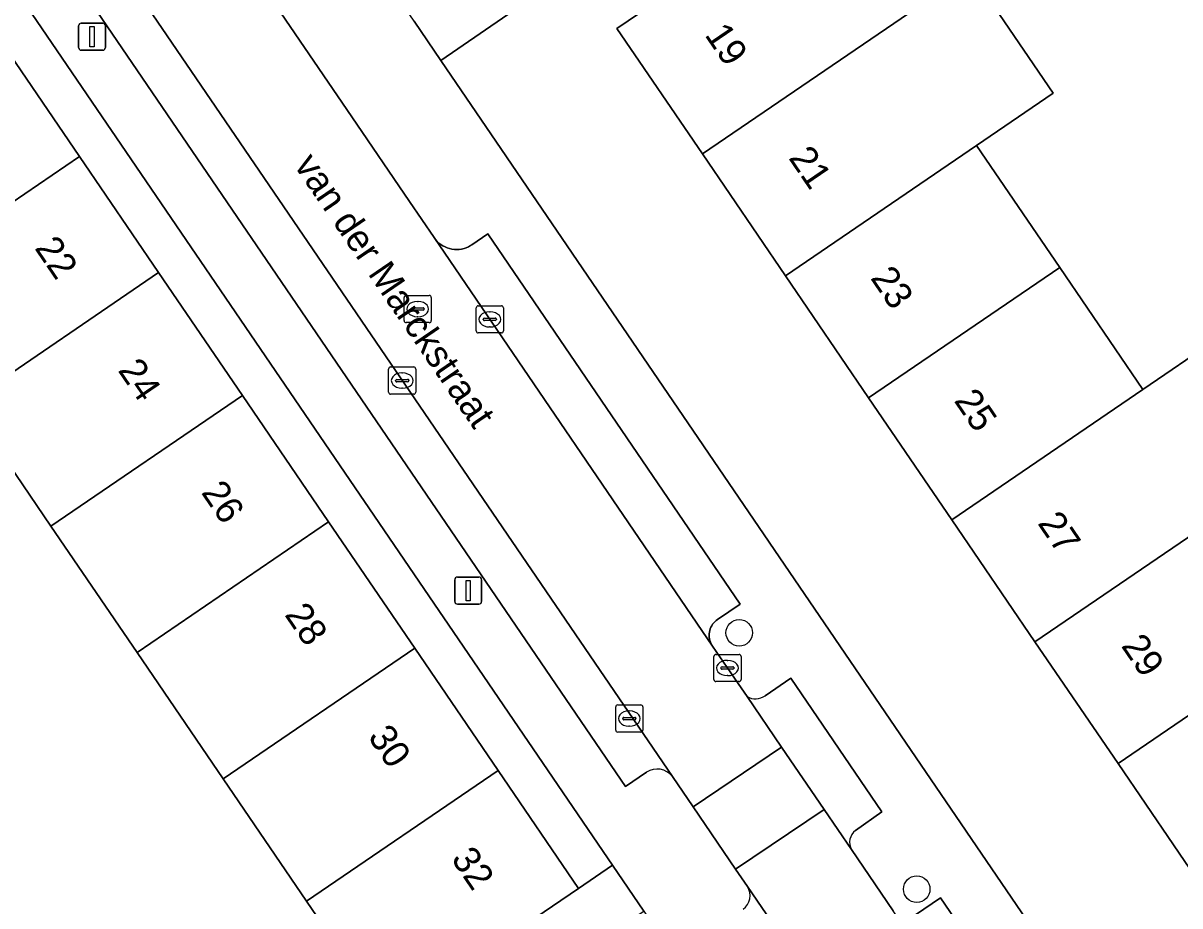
# Model space of a CAD drawing. Extents: x 157445 to 158888, y 383061 to 384688.
# Drawn here: x 158205.18 to 158247.77, y 383821.51 to 383854 of the extents above; entities that cross this region are included whole.
import ezdxf

# ---------------------------------------------------------------- set-up
doc = ezdxf.new("R2010")
doc.units = 0
for name, color, linetype in [('IMGEO_Boom', 7, 'Continuous'), ('IMGEO_Erf', 7, 'Continuous'), ('IMGEO_Kolk', 7, 'Continuous'), ('IMGEO_Lichtmast', 7, 'Continuous'), ('IMGEO_Openbare_ruimte_label', 7, 'Continuous'), ('IMGEO_Pand', 7, 'Continuous'), ('IMGEO_Pand_nummerreeks', 7, 'Continuous'), ('IMGEO_Parkeervlak_open', 7, 'Continuous'), ('IMGEO_Rijbaan_lokaal_open', 7, 'Continuous'), ('IMGEO_Rioolput', 7, 'Continuous'), ('IMGEO_Voetpad_open', 7, 'Continuous')]:
    doc.layers.add(name, color=color, linetype=linetype)

msp = doc.modelspace()

# ---------------------------------------------------------------- linework, layer by layer
at = {"layer": 'IMGEO_Boom'}
for centre in [(158231.547, 383831.557), (158238.081, 383822.12)]:
    msp.add_circle(centre, 0.489, dxfattribs=at)
at = {"layer": 'IMGEO_Erf'}
msp.add_lwpolyline([(158196.185, 383867.993), (158194.952, 383867.112), (158198.052, 383862.567), (158201.186, 383857.973), (158204.125, 383853.665), (158207.248, 383849.087), (158210.162, 383844.815), (158213.249, 383840.289), (158216.423, 383835.636), (158219.595, 383830.987), (158222.667, 383826.484), (158225.623, 383822.15), (158226.875, 383823.004)], close=True, dxfattribs=at)
for points in [[(158238.26, 383864.78), (158220.561, 383852.622), (158254.415, 383802.985), (158261.257, 383807.652), (158259.697, 383809.94), (158257.824, 383808.662), (158254.679, 383813.274), (158251.618, 383817.762), (158248.556, 383822.251), (158245.495, 383826.74), (158242.434, 383831.228), (158239.373, 383835.717), (158236.312, 383840.206), (158233.251, 383844.694), (158230.19, 383849.182), (158227.044, 383853.795), (158231.175, 383856.612)], [(158240.051, 383855.907), (158243.112, 383851.419), (158240.288, 383849.493), (158243.349, 383845.004), (158246.411, 383840.515), (158249.066, 383842.326)], [(158201.602, 383814.959), (158205.919, 383808.565), (158206.186, 383808.753), (158203.229, 383812.949), (158205.689, 383814.682), (158208.646, 383810.486), (158218.573, 383817.34), (158215.617, 383821.674), (158212.545, 383826.177), (158209.373, 383830.826), (158206.199, 383835.479), (158203.111, 383840.006)]]:
    msp.add_lwpolyline(points, dxfattribs=at)
at = {"layer": 'IMGEO_Kolk'}
for p, q in [((158221.862, 383842.667), (158221.862, 383843.519)), ((158221.937, 383843.593), (158222.789, 383843.593)), ((158222.863, 383843.519), (158222.863, 383842.667)), ((158222.121, 383843.087), (158222.121, 383843.099)), ((158222.559, 383843.05), (158222.161, 383843.05)), ((158222.164, 383843.136), (158222.562, 383843.136)), ((158222.35, 383843.373), (158222.375, 383843.373)), ((158222.605, 383843.099), (158222.605, 383843.087)), ((158222.373, 383842.813), (158222.348, 383842.813)), ((158222.789, 383842.593), (158221.937, 383842.593)), ((158218.71, 383841.34), (158219.562, 383841.34)), ((158218.635, 383840.414), (158218.635, 383841.266)), ((158219.123, 383841.12), (158219.148, 383841.12)), ((158219.636, 383841.266), (158219.636, 383840.414)), ((158218.894, 383840.834), (158218.894, 383840.846)), ((158219.332, 383840.797), (158218.934, 383840.797)), ((158218.937, 383840.883), (158219.335, 383840.883)), ((158219.146, 383840.56), (158219.121, 383840.56)), ((158219.378, 383840.846), (158219.378, 383840.834)), ((158219.562, 383840.34), (158218.71, 383840.34)), ((158230.613, 383829.835), (158230.613, 383830.687)), ((158230.688, 383830.761), (158231.54, 383830.761)), ((158231.614, 383830.687), (158231.614, 383829.835)), ((158230.872, 383830.255), (158230.872, 383830.267)), ((158230.915, 383830.304), (158231.313, 383830.304)), ((158231.101, 383830.541), (158231.126, 383830.541)), ((158231.356, 383830.267), (158231.356, 383830.255)), ((158231.31, 383830.218), (158230.912, 383830.218)), ((158231.124, 383829.981), (158231.099, 383829.981)), ((158231.54, 383829.761), (158230.688, 383829.761)), ((158226.997, 383827.974), (158226.997, 383828.826)), ((158227.072, 383828.9), (158227.924, 383828.9)), ((158227.485, 383828.68), (158227.51, 383828.68)), ((158227.998, 383828.826), (158227.998, 383827.974)), ((158227.256, 383828.394), (158227.256, 383828.406)), ((158227.694, 383828.357), (158227.296, 383828.357)), ((158227.299, 383828.443), (158227.697, 383828.443)), ((158227.74, 383828.406), (158227.74, 383828.394)), ((158227.924, 383827.9), (158227.072, 383827.9)), ((158227.508, 383828.12), (158227.483, 383828.12))]:
    msp.add_line(p, q, dxfattribs=at)
for points in [[(158221.862, 383842.667), (158221.862, 383843.519)], [(158221.937, 383843.593), (158222.789, 383843.593)], [(158222.863, 383843.519), (158222.863, 383842.667)], [(158222.789, 383842.593), (158221.937, 383842.593)], [(158218.71, 383841.34), (158219.562, 383841.34)], [(158218.635, 383840.414), (158218.635, 383841.266)], [(158219.636, 383841.266), (158219.636, 383840.414)], [(158219.562, 383840.34), (158218.71, 383840.34)], [(158230.613, 383829.835), (158230.613, 383830.687)], [(158230.688, 383830.761), (158231.54, 383830.761)], [(158231.614, 383830.687), (158231.614, 383829.835)], [(158231.54, 383829.761), (158230.688, 383829.761)], [(158226.997, 383827.974), (158226.997, 383828.826)], [(158227.072, 383828.9), (158227.924, 383828.9)], [(158227.998, 383828.826), (158227.998, 383827.974)], [(158227.924, 383827.9), (158227.072, 383827.9)]]:
    msp.add_lwpolyline(points, dxfattribs=at)
for centre, radius, start, end in [((158221.939, 383843.517), 0.0765, 91.552, 178.448), ((158221.939, 383843.517), 0.0765, 91.552, 178.448), ((158222.787, 383843.517), 0.0765, 1.552, 88.448), ((158222.787, 383843.517), 0.0765, 1.552, 88.448), ((158222.161, 383843.096), 0.0403, 85.8775, 175.7526), ((158222.158, 383843.086), 0.0366, 178.938, 274.7102), ((158222.562, 383843.093), 0.043, 264.8664, 352.4533), ((158222.566, 383843.098), 0.0386, 1.7309, 96.639), ((158221.939, 383842.669), 0.0765, 181.552, 268.448), ((158221.939, 383842.669), 0.0765, 181.552, 268.448), ((158222.787, 383842.669), 0.0765, 271.552, 358.448), ((158222.787, 383842.669), 0.0765, 271.552, 358.448), ((158218.712, 383841.264), 0.0765, 91.552, 178.448), ((158218.712, 383841.264), 0.0765, 91.552, 178.448), ((158219.56, 383841.264), 0.0765, 1.552, 88.448), ((158219.56, 383841.264), 0.0765, 1.552, 88.448), ((158218.934, 383840.843), 0.0403, 85.8775, 175.7526), ((158218.931, 383840.833), 0.0366, 178.938, 274.7102), ((158219.335, 383840.84), 0.043, 264.8664, 352.4533), ((158219.339, 383840.845), 0.0386, 1.7309, 96.639), ((158218.712, 383840.416), 0.0765, 181.552, 268.448), ((158218.712, 383840.416), 0.0765, 181.552, 268.448), ((158219.56, 383840.416), 0.0765, 271.552, 358.448), ((158219.56, 383840.416), 0.0765, 271.552, 358.448), ((158230.69, 383830.685), 0.0765, 91.552, 178.448), ((158230.69, 383830.685), 0.0765, 91.552, 178.448), ((158231.538, 383830.685), 0.0765, 1.552, 88.448), ((158231.538, 383830.685), 0.0765, 1.552, 88.448), ((158230.912, 383830.264), 0.0403, 85.8775, 175.7526), ((158230.909, 383830.254), 0.0366, 178.938, 274.7102), ((158231.313, 383830.261), 0.043, 264.8664, 352.4533), ((158231.317, 383830.266), 0.0386, 1.7309, 96.639), ((158230.69, 383829.837), 0.0765, 181.552, 268.448), ((158230.69, 383829.837), 0.0765, 181.552, 268.448), ((158231.538, 383829.837), 0.0765, 271.552, 358.448), ((158231.538, 383829.837), 0.0765, 271.552, 358.448), ((158227.074, 383828.824), 0.0765, 91.552, 178.448), ((158227.074, 383828.824), 0.0765, 91.552, 178.448), ((158227.922, 383828.824), 0.0765, 1.552, 88.448), ((158227.922, 383828.824), 0.0765, 1.552, 88.448), ((158227.296, 383828.403), 0.0403, 85.8775, 175.7526), ((158227.293, 383828.393), 0.0366, 178.938, 274.7102), ((158227.697, 383828.4), 0.043, 264.8664, 352.4533), ((158227.701, 383828.405), 0.0386, 1.7309, 96.639), ((158227.074, 383827.976), 0.0765, 181.552, 268.448), ((158227.074, 383827.976), 0.0765, 181.552, 268.448), ((158227.922, 383827.976), 0.0765, 271.552, 358.448), ((158227.922, 383827.976), 0.0765, 271.552, 358.448)]:
    msp.add_arc(centre, radius, start, end, dxfattribs=at)
for centre, major_axis, ratio, start_param, end_param in [((158222.349, 383843.093), (-0.387, 0.002), 0.722429, 4.712389, 7.853982), ((158222.374, 383843.093), (-0.39, 0.002), 0.717154, 1.570796, 4.712389), ((158219.122, 383840.84), (-0.387, 0.002), 0.722429, 4.712389, 7.853982), ((158219.147, 383840.84), (-0.39, 0.002), 0.717154, 1.570796, 4.712389), ((158231.1, 383830.261), (-0.387, 0.002), 0.722429, 4.712389, 7.853982), ((158231.125, 383830.261), (-0.39, 0.002), 0.717154, 1.570796, 4.712389), ((158227.484, 383828.4), (-0.387, 0.002), 0.722429, 4.712389, 7.853982), ((158227.509, 383828.4), (-0.39, 0.002), 0.717154, 1.570796, 4.712389)]:
    msp.add_ellipse(centre, major_axis=major_axis, ratio=ratio, start_param=start_param, end_param=end_param, dxfattribs=at)
at = {"layer": 'IMGEO_Lichtmast'}
for p, q in [((158207.217, 383853.097), (158207.217, 383853.897)), ((158207.217, 383853.897), (158207.217, 383853.097)), ((158207.317, 383853.997), (158208.107, 383853.997)), ((158208.107, 383853.997), (158207.317, 383853.997)), ((158208.207, 383853.897), (158208.207, 383853.097)), ((158208.207, 383853.097), (158208.207, 383853.897)), ((158208.107, 383852.997), (158207.317, 383852.997)), ((158207.317, 383852.997), (158208.107, 383852.997)), ((158221.071, 383832.71), (158221.071, 383833.51)), ((158221.071, 383833.51), (158221.071, 383832.71)), ((158221.171, 383833.61), (158221.961, 383833.61)), ((158221.961, 383833.61), (158221.171, 383833.61)), ((158222.061, 383833.51), (158222.061, 383832.71)), ((158222.061, 383832.71), (158222.061, 383833.51)), ((158221.961, 383832.61), (158221.171, 383832.61)), ((158221.171, 383832.61), (158221.961, 383832.61))]:
    msp.add_line(p, q, dxfattribs=at)
for points in [[(158207.637, 383853.872), (158207.787, 383853.872), (158207.787, 383853.122), (158207.637, 383853.122), (158207.637, 383853.872)], [(158221.491, 383833.485), (158221.641, 383833.485), (158221.641, 383832.735), (158221.491, 383832.735), (158221.491, 383833.485)]]:
    msp.add_lwpolyline(points, dxfattribs=at)
for centre, start, end in [((158207.317, 383853.897), 90, 180), ((158207.317, 383853.897), 90, 180), ((158208.107, 383853.897), 0, 90), ((158208.107, 383853.897), 360, 90), ((158207.317, 383853.097), 180, 270), ((158207.317, 383853.097), 180, 270), ((158208.107, 383853.097), 270, 0), ((158208.107, 383853.097), 270, 0), ((158221.171, 383833.51), 90, 180), ((158221.171, 383833.51), 90, 180), ((158221.961, 383833.51), 0, 90), ((158221.961, 383833.51), 360, 90), ((158221.171, 383832.71), 180, 270), ((158221.171, 383832.71), 180, 270), ((158221.961, 383832.71), 270, 0), ((158221.961, 383832.71), 270, 0)]:
    msp.add_arc(centre, 0.1, start, end, dxfattribs=at)
at = {"layer": 'IMGEO_Pand'}
for points in [[(158240.051, 383855.907), (158237.882, 383859.087), (158236.849, 383859.271), (158236.297, 383858.895), (158235.733, 383859.721), (158234.081, 383858.594), (158231.175, 383856.612), (158227.044, 383853.795), (158230.19, 383849.182)], [(158240.288, 383849.493), (158243.112, 383851.419), (158240.051, 383855.907), (158230.19, 383849.182), (158233.251, 383844.694)], [(158204.125, 383853.665), (158197.074, 383848.856), (158200.197, 383844.277), (158207.248, 383849.087)], [(158236.312, 383840.206), (158243.349, 383845.004), (158240.288, 383849.493), (158233.251, 383844.694)], [(158203.111, 383840.006), (158210.162, 383844.815), (158207.248, 383849.087), (158200.197, 383844.277)], [(158203.111, 383840.006), (158206.199, 383835.479), (158213.249, 383840.289), (158210.162, 383844.815)], [(158239.373, 383835.717), (158246.411, 383840.515), (158243.349, 383845.004), (158236.312, 383840.206)], [(158252.127, 383837.837), (158249.066, 383842.326), (158246.411, 383840.515), (158239.373, 383835.717), (158242.434, 383831.228), (158249.472, 383836.027)], [(158216.423, 383835.636), (158213.249, 383840.289), (158206.199, 383835.479), (158209.373, 383830.826)], [(158249.472, 383836.027), (158242.434, 383831.228), (158245.495, 383826.74), (158252.532, 383831.539)], [(158219.595, 383830.987), (158216.423, 383835.636), (158209.373, 383830.826), (158212.545, 383826.177)], [(158252.532, 383831.539), (158245.495, 383826.74), (158248.556, 383822.251), (158255.594, 383827.05)], [(158219.595, 383830.987), (158212.545, 383826.177), (158215.617, 383821.674), (158222.667, 383826.484)], [(158222.667, 383826.484), (158215.617, 383821.674), (158218.573, 383817.34), (158221.493, 383819.332), (158225.623, 383822.15)]]:
    msp.add_lwpolyline(points, close=True, dxfattribs=at)
at = {"layer": 'IMGEO_Parkeervlak_open'}
for points in [[(158229.086, 383826.263), (158200.985, 383867.438), (158199.637, 383866.518), (158227.36, 383825.895), (158228.131, 383826.421)], [(158235.823, 383824.282), (158236.799, 383824.964), (158233.445, 383829.881), (158232.5, 383829.24)], [(158231.833, 383829.207), (158233.106, 383827.345), (158234.672, 383825.051), (158235.678, 383823.579)], [(158248.151, 383798.359), (158247.776, 383798.907), (158231.849, 383822.216)], [(158248.248, 383808.187), (158238.955, 383821.804), (158238.036, 383821.177)]]:
    msp.add_lwpolyline(points, dxfattribs=at)
msp.add_lwpolyline([(158220.309, 383846.103), (158230.56, 383831.07), (158230.538, 383831.105), (158230.508, 383831.159), (158230.483, 383831.216), (158230.464, 383831.276), (158230.45, 383831.336), (158230.441, 383831.398), (158230.438, 383831.46), (158230.44, 383831.522), (158230.448, 383831.584), (158230.461, 383831.645), (158230.48, 383831.704), (158230.504, 383831.762), (158230.533, 383831.817), (158230.567, 383831.869), (158230.606, 383831.918), (158230.648, 383831.964), (158230.695, 383832.005), (158230.745, 383832.042), (158231.582, 383832.612), (158222.289, 383846.241), (158221.699, 383845.839), (158221.656, 383845.811), (158221.578, 383845.768), (158221.496, 383845.732), (158221.411, 383845.704), (158221.324, 383845.683), (158221.236, 383845.67), (158221.146, 383845.665), (158221.057, 383845.669), (158220.968, 383845.68), (158220.881, 383845.698), (158220.795, 383845.725), (158220.713, 383845.759), (158220.634, 383845.801), (158220.558, 383845.849), (158220.488, 383845.904), (158220.422, 383845.965), (158220.363, 383846.031)], close=True, dxfattribs=at)
for centre, radius, start, end in [((158232.14, 383829.752), 0.625, 240.5605, 305.1043), ((158228.526, 383825.844), 0.699, 36.8051, 124.4065), ((158236.167, 383823.845), 0.556, 128.1835, 208.5078), ((158231.317, 383821.884), 0.627, 306.6467, 31.9234)]:
    msp.add_arc(centre, radius, start, end, dxfattribs=at)
at = {"layer": 'IMGEO_Rijbaan_lokaal_open'}
msp.add_lwpolyline([(158200.985, 383867.438), (158229.086, 383826.263), (158229.849, 383825.146), (158233.106, 383827.345), (158231.833, 383829.207), (158231.501, 383829.694), (158230.56, 383831.07), (158220.309, 383846.103), (158219.405, 383847.428), (158217.28, 383850.544), (158214.135, 383855.156), (158209.097, 383862.544), (158208.198, 383863.863), (158204.811, 383868.829)], dxfattribs=at)
for points in [[(158233.106, 383827.345), (158229.849, 383825.146), (158231.411, 383822.857), (158234.672, 383825.051)], [(158247.776, 383798.907), (158251.028, 383801.074), (158249.448, 383803.39), (158247.114, 383806.809), (158237.215, 383821.317), (158236.772, 383821.968), (158235.678, 383823.579), (158234.672, 383825.051), (158231.411, 383822.857), (158231.849, 383822.216)]]:
    msp.add_lwpolyline(points, close=True, dxfattribs=at)
at = {"layer": 'IMGEO_Rioolput'}
for p, q in [((158219.206, 383843.046), (158219.206, 383843.898)), ((158219.281, 383843.972), (158220.133, 383843.972)), ((158220.207, 383843.898), (158220.207, 383843.046)), ((158219.465, 383843.466), (158219.465, 383843.478)), ((158219.508, 383843.515), (158219.906, 383843.515)), ((158219.694, 383843.752), (158219.719, 383843.752)), ((158219.949, 383843.478), (158219.949, 383843.466)), ((158219.903, 383843.429), (158219.505, 383843.429)), ((158219.717, 383843.192), (158219.692, 383843.192)), ((158220.133, 383842.972), (158219.281, 383842.972))]:
    msp.add_line(p, q, dxfattribs=at)
for points in [[(158219.206, 383843.046), (158219.206, 383843.898)], [(158219.281, 383843.972), (158220.133, 383843.972)], [(158220.207, 383843.898), (158220.207, 383843.046)], [(158220.133, 383842.972), (158219.281, 383842.972)]]:
    msp.add_lwpolyline(points, dxfattribs=at)
for centre, radius, start, end in [((158219.283, 383843.896), 0.0765, 91.552, 178.448), ((158219.283, 383843.896), 0.0765, 91.552, 178.448), ((158220.131, 383843.896), 0.0765, 1.552, 88.448), ((158220.131, 383843.896), 0.0765, 1.552, 88.448), ((158219.505, 383843.475), 0.0403, 85.8775, 175.7526), ((158219.502, 383843.465), 0.0366, 178.938, 274.7102), ((158219.906, 383843.472), 0.043, 264.8664, 352.4533), ((158219.91, 383843.477), 0.0386, 1.7309, 96.639), ((158219.283, 383843.048), 0.0765, 181.552, 268.448), ((158219.283, 383843.048), 0.0765, 181.552, 268.448), ((158220.131, 383843.048), 0.0765, 271.552, 358.448), ((158220.131, 383843.048), 0.0765, 271.552, 358.448)]:
    msp.add_arc(centre, radius, start, end, dxfattribs=at)
for centre, major_axis, ratio, start_param, end_param in [((158219.693, 383843.472), (-0.387, 0.002), 0.722429, 4.712389, 7.853982), ((158219.718, 383843.472), (-0.39, 0.002), 0.717154, 1.570796, 4.712389)]:
    msp.add_ellipse(centre, major_axis=major_axis, ratio=ratio, start_param=start_param, end_param=end_param, dxfattribs=at)
at = {"layer": 'IMGEO_Voetpad_open'}
for points in [[(158228.131, 383826.421), (158227.36, 383825.895), (158199.637, 383866.518), (158200.985, 383867.438), (158200.299, 383871.042), (158199.317, 383872.492), (158198.439, 383871.898), (158194.154, 383878.226), (158195.032, 383878.82), (158194.14, 383880.137), (158190.985, 383882.115), (158189.586, 383881.16), (158171.542, 383907.579)], [(158220.561, 383852.622), (158219.571, 383854.073), (158205.651, 383874.482), (158204.324, 383876.428), (158205.233, 383877.954), (158203.861, 383880.09)], [(158194.101, 383870.467), (158194.761, 383869.498), (158196.185, 383867.993), (158226.875, 383823.004), (158228.035, 383821.305), (158259.806, 383774.732), (158260.785, 383773.297), (158262.353, 383771.002), (158266.902, 383764.36), (158268.557, 383761.942), (158273.392, 383754.863), (158276.273, 383750.703), (158281.209, 383754.075), (158280.976, 383754.417), (158277.966, 383758.835), (158276.8, 383760.196), (158276.019, 383760.753), (158273.675, 383762.423), (158273.097, 383762.835), (158272.742, 383762.581), (158271.393, 383761.66), (158265.115, 383770.703), (158266.189, 383771.436)], [(158219.571, 383854.073), (158220.561, 383852.622), (158238.26, 383864.78)], [(158214.135, 383855.156), (158217.28, 383850.544), (158219.405, 383847.428), (158220.309, 383846.103), (158220.363, 383846.031), (158220.422, 383845.965), (158220.488, 383845.904), (158220.558, 383845.849), (158220.634, 383845.801), (158220.713, 383845.759), (158220.795, 383845.725), (158220.881, 383845.698), (158220.968, 383845.68), (158221.057, 383845.669), (158221.146, 383845.665), (158221.236, 383845.67), (158221.324, 383845.683), (158221.411, 383845.704), (158221.496, 383845.732), (158221.578, 383845.768), (158221.656, 383845.811), (158221.699, 383845.839), (158222.289, 383846.241), (158231.582, 383832.612), (158230.745, 383832.042), (158230.695, 383832.005), (158230.648, 383831.964), (158230.606, 383831.918), (158230.567, 383831.869), (158230.533, 383831.817), (158230.504, 383831.762), (158230.48, 383831.704), (158230.461, 383831.645), (158230.448, 383831.584), (158230.44, 383831.522), (158230.438, 383831.46), (158230.441, 383831.398), (158230.45, 383831.336), (158230.464, 383831.276), (158230.483, 383831.216), (158230.508, 383831.159), (158230.538, 383831.105), (158230.56, 383831.07), (158231.501, 383829.694), (158231.833, 383829.207)], [(158269.302, 383781.158), (158255.342, 383801.626), (158254.415, 383802.985), (158220.561, 383852.622)], [(158232.5, 383829.24), (158233.445, 383829.881), (158236.799, 383824.964), (158235.823, 383824.282)], [(158231.849, 383822.216), (158231.411, 383822.857), (158229.849, 383825.146), (158229.086, 383826.263)], [(158235.678, 383823.579), (158236.772, 383821.968), (158237.215, 383821.317)], [(158216.726, 383793.206), (158214.651, 383796.198), (158212.195, 383799.739), (158210.456, 383802.148), (158208.198, 383805.662), (158206.994, 383807.536), (158228.035, 383821.305), (158226.875, 383823.004), (158225.623, 383822.15), (158221.493, 383819.332), (158218.573, 383817.34), (158208.646, 383810.486), (158206.186, 383808.753), (158205.919, 383808.565), (158201.602, 383814.959)], [(158238.036, 383821.177), (158238.955, 383821.804), (158248.248, 383808.187)]]:
    msp.add_lwpolyline(points, dxfattribs=at)
for centre, radius, start, end in [((158232.14, 383829.752), 0.625, 240.5605, 305.1043), ((158228.526, 383825.844), 0.699, 36.8051, 124.4065), ((158236.167, 383823.845), 0.556, 128.1835, 208.5078), ((158231.317, 383821.884), 0.627, 306.6467, 31.9234)]:
    msp.add_arc(centre, radius, start, end, dxfattribs=at)

# ---------------------------------------------------------------- texts
at = {"layer": 'IMGEO_Openbare_ruimte_label'}
msp.add_text('van der Marckstraat', height=1, rotation=304.3256, dxfattribs=at).set_placement((158215.127, 383848.769))
at = {"layer": 'IMGEO_Pand_nummerreeks'}
for s, rotation, p in [('19', 304.2913, (158230.251, 383853.565)), ('21', 304.2913, (158233.341, 383849.034)), ('22', 304.3, (158205.577, 383845.716)), ('23', 304.2934, (158236.355, 383844.614)), ('24', 304.3, (158208.645, 383841.217)), ('25', 304.2934, (158239.433, 383840.1)), ('26', 304.3, (158211.712, 383836.72)), ('27', 304.2913, (158242.511, 383835.587)), ('28', 304.3, (158214.782, 383832.222)), ('29', 304.2934, (158245.589, 383831.074)), ('30', 304.3, (158217.849, 383827.726)), ('32', 304.3, (158220.913, 383823.235))]:
    msp.add_text(s, height=1, rotation=rotation, dxfattribs=at).set_placement(p)

doc.saveas('drawing.dxf')
